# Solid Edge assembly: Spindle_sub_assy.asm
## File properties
Author: Impact Mechanic Lab
Template: Iso Metric Assembly.asm
Last saved by: Impact Mechanic Lab
Revision: 2
Application: Solid Edge
Username: Impact Mechanic Lab
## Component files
spindle.par
Ball.par
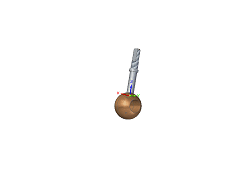
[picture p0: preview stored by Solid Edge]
